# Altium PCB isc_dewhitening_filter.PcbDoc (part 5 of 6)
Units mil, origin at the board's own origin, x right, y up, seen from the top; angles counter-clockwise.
Board outline 8440 x 7000 mil, 6 copper layers (Top Layer, MidLayer1, InternalPlane1, Internal Plane 3, InternalPlane2, Bottom Layer); 550 components, 462 nets, 2189 pads, 795 vias.
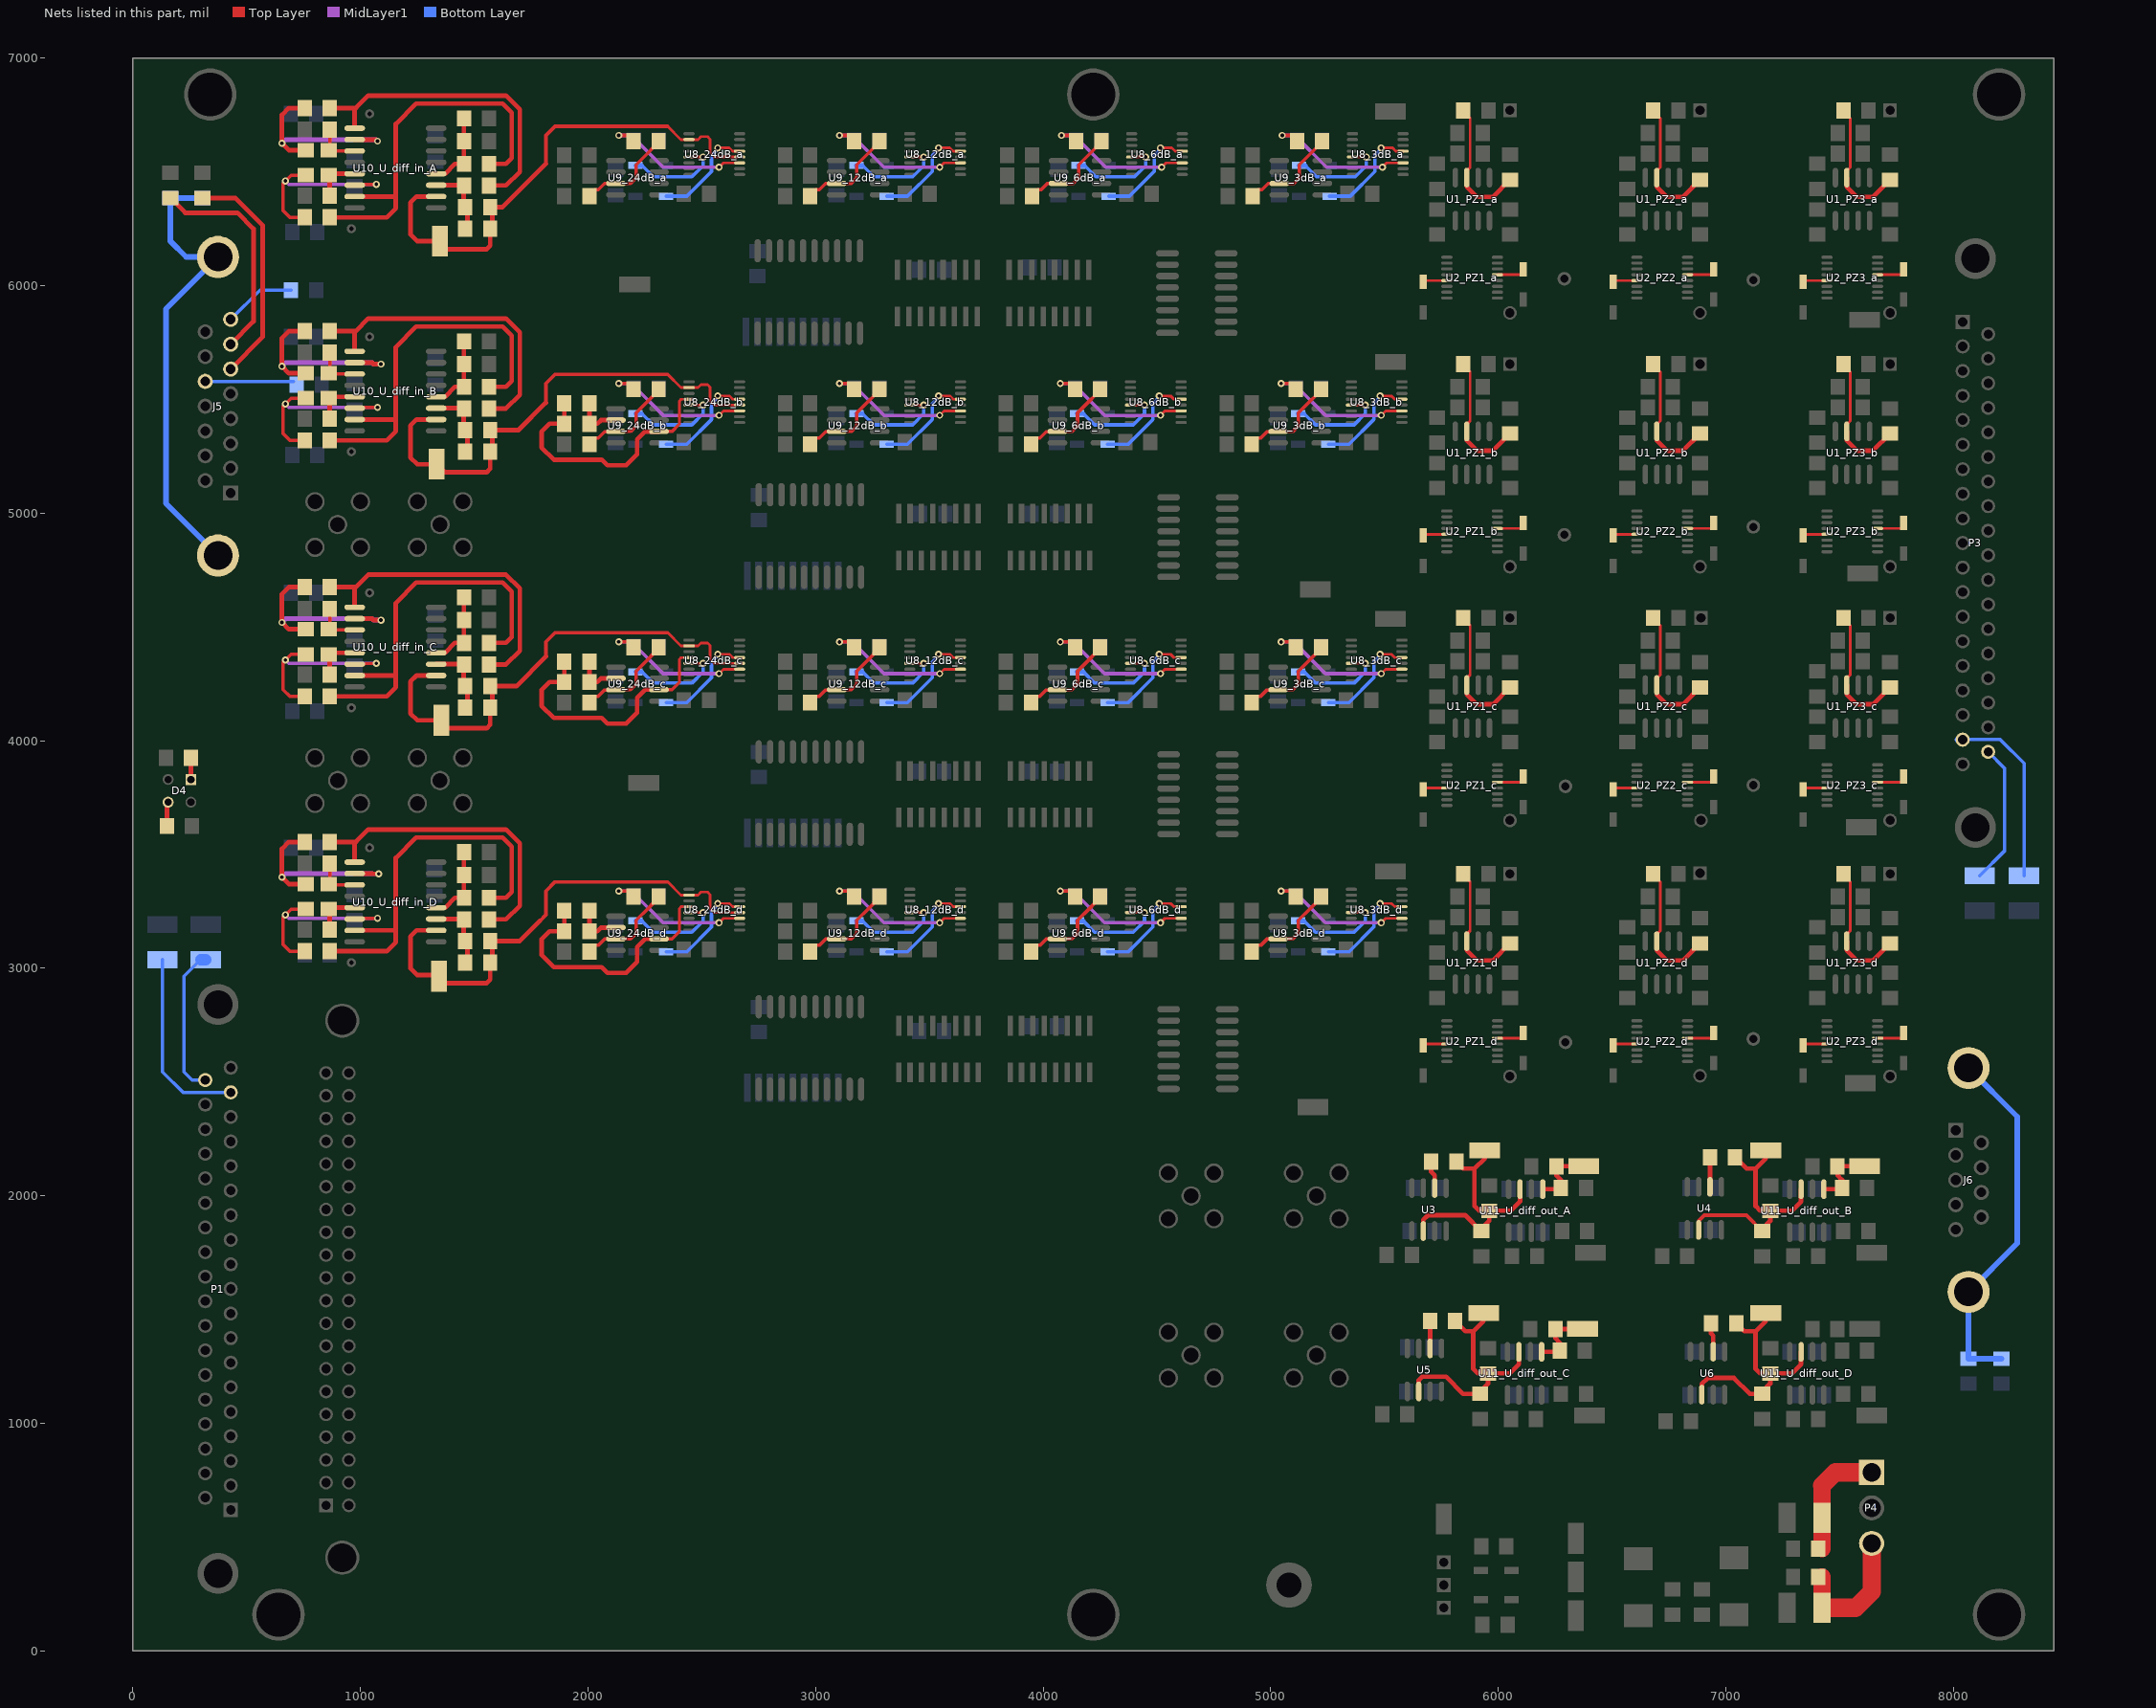
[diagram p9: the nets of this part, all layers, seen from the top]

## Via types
v1: diameter 31, hole 16, Top Layer to Bottom Layer, 794 vias
v2: diameter 45, hole 20, Top Layer to Bottom Layer, 1 vias

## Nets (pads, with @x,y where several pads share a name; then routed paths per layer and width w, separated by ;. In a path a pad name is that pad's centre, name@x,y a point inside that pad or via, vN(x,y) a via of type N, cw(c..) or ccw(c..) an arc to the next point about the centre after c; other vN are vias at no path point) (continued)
NetC27_24dB_b_1: C27_24dB_b.1 R13_24dB_b.2 U8_24dB_b.12 U9_24dB_b.6 | length 1154.7
  Top Layer w12: 2401,5391 2401,5492.5 2409.09,5500.59 U8_24dB_b.12@2426.67,5500.59
  Top Layer w15: U9_24dB_b.6@2311.49,5359 2369,5359 2401,5391
  Top Layer w20: C27_24dB_b.1@1895.88,5483 R13_24dB_b.2@1895.88,5393 1831,5393 1796,5358 1796,5289 1850,5235 2060,5235 2085,5210 2168,5210 2216,5258 2216,5323 2252,5359 U9_24dB_b.6@2311.49,5359
NetC27_24dB_b_2: C27_24dB_b.2 R13_24dB_b.1 U9_24dB_b.2 | length 213
  Top Layer w20: C27_24dB_b.2@2006.12,5483 R13_24dB_b.1@2006.12,5393 2041,5393 2057,5409 U9_24dB_b.2@2122.51,5409
NetC27_24dB_c_1: C27_24dB_c.1 R13_24dB_c.2 U8_24dB_c.12 U9_24dB_c.6 | length 1154.7
  Top Layer w12: 2401,4256 2401,4357.5 2409.09,4365.59 U8_24dB_c.12@2426.67,4365.59
  Top Layer w15: U9_24dB_c.6@2311.49,4224 2369,4224 2401,4256
  Top Layer w20: C27_24dB_c.1@1895.88,4348 R13_24dB_c.2@1895.88,4258 1831,4258 1796,4223 1796,4154 1850,4100 2060,4100 2085,4075 2168,4075 2216,4123 2216,4188 2252,4224 U9_24dB_c.6@2311.49,4224
NetC27_24dB_c_2: C27_24dB_c.2 R13_24dB_c.1 U9_24dB_c.2 | length 213
  Top Layer w20: C27_24dB_c.2@2006.12,4348 R13_24dB_c.1@2006.12,4258 2041,4258 2057,4274 U9_24dB_c.2@2122.51,4274
NetC27_24dB_d_1: C27_24dB_d.1 R13_24dB_d.2 U8_24dB_d.12 U9_24dB_d.6 | length 1154.7
  Top Layer w12: 2401,3161 2401,3262.5 2409.09,3270.59 U8_24dB_d.12@2426.67,3270.59
  Top Layer w15: U9_24dB_d.6@2311.49,3129 2369,3129 2401,3161
  Top Layer w20: C27_24dB_d.1@1895.88,3253 R13_24dB_d.2@1895.88,3163 1831,3163 1796,3128 1796,3059 1850,3005 2060,3005 2085,2980 2168,2980 2216,3028 2216,3093 2252,3129 U9_24dB_d.6@2311.49,3129
NetC27_24dB_d_2: C27_24dB_d.2 R13_24dB_d.1 U9_24dB_d.2 | length 213
  Top Layer w20: C27_24dB_d.2@2006.12,3253 R13_24dB_d.1@2006.12,3163 2041,3163 2057,3179 U9_24dB_d.2@2122.51,3179
NetC34_2: C34.2 J5.16 J5.17 R34.2 | length 2069.1
  Bottom Layer w25: R34.2@305,6384.88 C34.2@165,6384.88 165,6195 234.09,6125.91 J5.17@374.02,6125.91 145,5896.89 145,5043.11 J5.16@374.02,4814.09
NetC35_2: C35.2 J6.10 J6.11 R37.2 | length 1599.1
  Bottom Layer w25: C35.2@8065,1285.12 R37.2@8210,1285.12 ; C35.2@8065.98,1285.12 J6.11@8065.98,1578.07 8280,1792.09 8280,2347.91 J6.10@8065.98,2561.93
NetC37_U_diff_in_A_2: C37_U_diff_in_A.2 R15_U_diff_in_A.1 R16_U_diff_in_A.1 U10_U_diff_in_A.12 | length 340.1
  Top Layer w20: U10_U_diff_in_A.12@1332.8,6491.5 1371.5,6491.5 1415,6535 R15_U_diff_in_A.1@1454.88,6535 R16_U_diff_in_A.1@1454.88,6635 C37_U_diff_in_A.2@1454.88,6735
NetC37_U_diff_in_B_2: C37_U_diff_in_B.2 R15_U_diff_in_B.1 R16_U_diff_in_B.1 U10_U_diff_in_B.12 | length 340.1
  Top Layer w20: U10_U_diff_in_B.12@1332.8,5511.5 1371.5,5511.5 1415,5555 R15_U_diff_in_B.1@1454.88,5555 R16_U_diff_in_B.1@1454.88,5655 C37_U_diff_in_B.2@1454.88,5755
NetC37_U_diff_in_C_2: C37_U_diff_in_C.2 R15_U_diff_in_C.1 R16_U_diff_in_C.1 U10_U_diff_in_C.12 | length 340.1
  Top Layer w20: U10_U_diff_in_C.12@1332.8,4386.5 1371.5,4386.5 1415,4430 R15_U_diff_in_C.1@1454.88,4430 R16_U_diff_in_C.1@1454.88,4530 C37_U_diff_in_C.2@1454.88,4630
NetC37_U_diff_in_D_2: C37_U_diff_in_D.2 R15_U_diff_in_D.1 R16_U_diff_in_D.1 U10_U_diff_in_D.12 | length 340.1
  Top Layer w20: U10_U_diff_in_D.12@1332.8,3266.5 1371.5,3266.5 1415,3310 R15_U_diff_in_D.1@1454.88,3310 R16_U_diff_in_D.1@1454.88,3410 C37_U_diff_in_D.2@1454.88,3510
NetC38_U_diff_in_A_1: C38_U_diff_in_A.1 R33_U_diff_in_A.1 U10_U_diff_in_A.3 | length 195.7
  Top Layer w15: C38_U_diff_in_A.1@863.62,6591.5 U10_U_diff_in_A.3@974.53,6591.5 ; C38_U_diff_in_A.1@865.12,6600.24 R33_U_diff_in_A.1@865.12,6685
NetC38_U_diff_in_A_2: C38_U_diff_in_A.2 R32_U_diff_in_A.1 U10_U_diff_in_A.5 | length 192.7
  Top Layer w20: R32_U_diff_in_A.1@865.12,6395 C38_U_diff_in_A.2@865.12,6479.76 ; C38_U_diff_in_A.2@866.61,6491.5 U10_U_diff_in_A.5@974.53,6491.5
NetC38_U_diff_in_B_1: C38_U_diff_in_B.1 R33_U_diff_in_B.1 U10_U_diff_in_B.3 | length 195.7
  Top Layer w15: C38_U_diff_in_B.1@863.62,5611.5 U10_U_diff_in_B.3@974.53,5611.5 ; C38_U_diff_in_B.1@865.12,5620.24 R33_U_diff_in_B.1@865.12,5705
NetC38_U_diff_in_B_2: C38_U_diff_in_B.2 R32_U_diff_in_B.1 U10_U_diff_in_B.5 | length 192.7
  Top Layer w20: R32_U_diff_in_B.1@865.12,5415 C38_U_diff_in_B.2@865.12,5499.76 ; C38_U_diff_in_B.2@866.61,5511.5 U10_U_diff_in_B.5@974.53,5511.5
NetC38_U_diff_in_C_1: C38_U_diff_in_C.1 R33_U_diff_in_C.1 U10_U_diff_in_C.3 | length 195.7
  Top Layer w15: C38_U_diff_in_C.1@863.62,4486.5 U10_U_diff_in_C.3@974.53,4486.5 ; C38_U_diff_in_C.1@865.12,4495.24 R33_U_diff_in_C.1@865.12,4580
NetC38_U_diff_in_C_2: C38_U_diff_in_C.2 R32_U_diff_in_C.1 U10_U_diff_in_C.5 | length 192.7
  Top Layer w20: R32_U_diff_in_C.1@865.12,4290 C38_U_diff_in_C.2@865.12,4374.76 ; C38_U_diff_in_C.2@866.61,4386.5 U10_U_diff_in_C.5@974.53,4386.5
NetC38_U_diff_in_D_1: C38_U_diff_in_D.1 R33_U_diff_in_D.1 U10_U_diff_in_D.3 | length 195.7
  Top Layer w15: C38_U_diff_in_D.1@863.62,3366.5 U10_U_diff_in_D.3@974.53,3366.5 ; C38_U_diff_in_D.1@865.12,3375.24 R33_U_diff_in_D.1@865.12,3460
NetC38_U_diff_in_D_2: C38_U_diff_in_D.2 R32_U_diff_in_D.1 U10_U_diff_in_D.5 | length 192.7
  Top Layer w20: R32_U_diff_in_D.1@865.12,3170 C38_U_diff_in_D.2@865.12,3254.76 ; C38_U_diff_in_D.2@866.61,3266.5 U10_U_diff_in_D.5@974.53,3266.5
NetC39_U_diff_in_A_1: C39_U_diff_in_A.1 R20_U_diff_in_A.2 R21_U_diff_in_A.1 U10_U_diff_in_A.11 | length 321
  Top Layer w20: U10_U_diff_in_A.11@1332.8,6441.5 R21_U_diff_in_A.1@1453.39,6441.5 ; R21_U_diff_in_A.1@1454.88,6440 R21_U_diff_in_A.1@1453.39,6441.5 ; C39_U_diff_in_A.1@1469.88,6250 1469.88,6330 1453.39,6346.5 R21_U_diff_in_A.1@1453.39,6441.5
NetC39_U_diff_in_A_2: C39_U_diff_in_A.2 R20_U_diff_in_A.1 TP1.1 U8_24dB_a.4 U8_24dB_a.10 U10_U_diff_in_A.10 | length 2232.6
  Top Layer w12: 2350,6700 2408.23,6641.77 U8_24dB_a.10@2443.78,6641.77 2483.23,6641.77 2496.46,6655 2525,6655 2536.5,6643.5 2536.5,6583.5 2555,6565 U8_24dB_a.4@2666.22,6565
  Top Layer w15: 1815,6535 1815,6660 1855,6700 2350,6700
  Top Layer w20: U10_U_diff_in_A.10@1332.8,6391.5 1246.5,6391.5 1220,6365 1220,6225 1250,6195 1335,6195 1370,6160 1555,6160 1570.12,6175.12 C39_U_diff_in_A.2@1570.12,6250 ; C39_U_diff_in_A.2@1580,6249.88 1580.12,6250 1580.12,6340 1575.12,6345 1625,6345 1815,6535
NetC39_U_diff_in_B_1: C39_U_diff_in_B.1 R20_U_diff_in_B.2 R21_U_diff_in_B.1 U10_U_diff_in_B.11 | length 321
  Top Layer w20: U10_U_diff_in_B.11@1332.8,5461.5 R21_U_diff_in_B.1@1453.39,5461.5 ; R21_U_diff_in_B.1@1454.88,5460 R21_U_diff_in_B.1@1453.39,5461.5 ; C39_U_diff_in_B.1@1469.88,5270 1469.88,5350 1453.39,5366.5 R21_U_diff_in_B.1@1453.39,5461.5
NetC39_U_diff_in_B_2: C39_U_diff_in_B.2 R20_U_diff_in_B.1 TP14.1 U8_24dB_b.4 U8_24dB_b.10 U10_U_diff_in_B.10 | length 2163.6
  Top Layer w12: 2350,5610 2408.23,5551.77 U8_24dB_b.10@2443.78,5551.77 2483.23,5551.77 2496.46,5565 2525,5565 2536.5,5553.5 2536.5,5493.5 2555,5475 U8_24dB_b.4@2666.22,5475
  Top Layer w15: 1815,5485 1815,5570 1855,5610 2350,5610
  Top Layer w20: U10_U_diff_in_B.10@1332.8,5411.5 1246.5,5411.5 1220,5385 1220,5245 1250,5215 TP14.1@1335,5215 1370,5180 1555,5180 1570.12,5195.12 C39_U_diff_in_B.2@1570.12,5270 ; C39_U_diff_in_B.2@1580,5269.88 1580.12,5270 1580.12,5360 1575.12,5365 1695,5365 1815,5485
NetC39_U_diff_in_C_1: C39_U_diff_in_C.1 R20_U_diff_in_C.2 R21_U_diff_in_C.1 U10_U_diff_in_C.11 | length 321
  Top Layer w20: U10_U_diff_in_C.11@1332.8,4336.5 R21_U_diff_in_C.1@1453.39,4336.5 ; R21_U_diff_in_C.1@1454.88,4335 R21_U_diff_in_C.1@1453.39,4336.5 ; C39_U_diff_in_C.1@1469.88,4145 1469.88,4225 1453.39,4241.5 R21_U_diff_in_C.1@1453.39,4336.5
NetC39_U_diff_in_C_2: C39_U_diff_in_C.2 R20_U_diff_in_C.1 TP17.1 U8_24dB_c.4 U8_24dB_c.10 U10_U_diff_in_C.10 | length 2100
  Top Layer w12: 2350,4475 2408.23,4416.77 U8_24dB_c.10@2443.78,4416.77 2483.23,4416.77 2496.46,4430 2525,4430 2536.5,4418.5 2536.5,4358.5 2555,4340 U8_24dB_c.4@2666.22,4340
  Top Layer w15: 1815,4370 1815,4435 1855,4475 2350,4475
  Top Layer w20: U10_U_diff_in_C.10@1332.8,4286.5 1246.5,4286.5 1220,4260 1220,4120 1250,4090 TP17.1@1335,4090 ; TP17.1@1370,4055 1555,4055 1570.12,4070.12 C39_U_diff_in_C.2@1570.12,4145 ; C39_U_diff_in_C.2@1580,4144.88 1580.12,4145 1580.12,4235 1575.12,4240 1685,4240 1815,4370 1816.25,4371.25
NetC39_U_diff_in_D_1: C39_U_diff_in_D.1 R20_U_diff_in_D.2 R21_U_diff_in_D.1 U10_U_diff_in_D.11 | length 321
  Top Layer w20: U10_U_diff_in_D.11@1332.8,3216.5 R21_U_diff_in_D.1@1453.39,3216.5 ; R21_U_diff_in_D.1@1454.88,3215 R21_U_diff_in_D.1@1453.39,3216.5 ; C39_U_diff_in_D.1@1469.88,3025 1469.88,3105 1453.39,3121.5 R21_U_diff_in_D.1@1453.39,3216.5
NetC39_U_diff_in_D_2: C39_U_diff_in_D.2 R20_U_diff_in_D.1 TP20.1 U8_24dB_d.4 U8_24dB_d.10 U10_U_diff_in_D.10 | length 2132
  Top Layer w12: 2350,3380 2408.23,3321.77 U8_24dB_d.10@2443.78,3321.77 2483.23,3321.77 2496.46,3335 2525,3335 2536.5,3323.5 2536.5,3263.5 2555,3245 U8_24dB_d.4@2666.22,3245
  Top Layer w15: 1787.5,3207.5 1815,3235 1815,3340 1855,3380 2350,3380
  Top Layer w20: U10_U_diff_in_D.10@1332.8,3166.5 1246.5,3166.5 1220,3140 1220,3000 1250,2970 TP20.1@1335,2970 ; TP20.1@1370,2935 1555,2935 1570.12,2950.12 C39_U_diff_in_D.2@1570.12,3025 ; C39_U_diff_in_D.2@1580,3024.88 1580.12,3025 1580.12,3115 1575.12,3120 1700,3120 1787.5,3207.5
NetD1_PZ1_a_1: D1_PZ1_a.1 U2_PZ1_a.5 | length 109
  Top Layer w12: D1_PZ1_a.1@5672.8,6022.2 U2_PZ1_a.5@5773.78,6022.2 ; D1_PZ1_a.1@5676.93,6031.95 D1_PZ1_a.1@5676.93,6040
NetD1_PZ1_b_1: D1_PZ1_b.1 U2_PZ1_b.5 | length 109
  Top Layer w12: D1_PZ1_b.1@5672.8,4907.2 U2_PZ1_b.5@5773.78,4907.2 ; D1_PZ1_b.1@5676.93,4916.95 D1_PZ1_b.1@5676.93,4925
NetD1_PZ1_c_1: D1_PZ1_c.1 U2_PZ1_c.5 | length 109
  Top Layer w12: D1_PZ1_c.1@5672.8,3792.2 U2_PZ1_c.5@5773.78,3792.2 ; D1_PZ1_c.1@5676.93,3801.95 D1_PZ1_c.1@5676.93,3810
NetD1_PZ1_d_1: D1_PZ1_d.1 U2_PZ1_d.5 | length 109
  Top Layer w12: D1_PZ1_d.1@5672.8,2667.2 U2_PZ1_d.5@5773.78,2667.2 ; D1_PZ1_d.1@5676.93,2676.95 D1_PZ1_d.1@5676.93,2685
NetD1_PZ2_a_1: D1_PZ2_a.1 U2_PZ2_a.5 | length 109
  Top Layer w12: D1_PZ2_a.1@6507.8,6022.2 U2_PZ2_a.5@6608.78,6022.2 ; D1_PZ2_a.1@6511.93,6031.95 D1_PZ2_a.1@6511.93,6040
NetD1_PZ2_b_1: D1_PZ2_b.1 U2_PZ2_b.5 | length 109
  Top Layer w12: D1_PZ2_b.1@6507.8,4907.2 U2_PZ2_b.5@6608.78,4907.2 ; D1_PZ2_b.1@6511.93,4916.95 D1_PZ2_b.1@6511.93,4925
NetD1_PZ2_c_1: D1_PZ2_c.1 U2_PZ2_c.5 | length 109
  Top Layer w12: D1_PZ2_c.1@6507.8,3792.2 U2_PZ2_c.5@6608.78,3792.2 ; D1_PZ2_c.1@6511.93,3801.95 D1_PZ2_c.1@6511.93,3810
NetD1_PZ2_d_1: D1_PZ2_d.1 U2_PZ2_d.5 | length 109
  Top Layer w12: D1_PZ2_d.1@6507.8,2667.2 U2_PZ2_d.5@6608.78,2667.2 ; D1_PZ2_d.1@6511.93,2676.95 D1_PZ2_d.1@6511.93,2685
NetD1_PZ3_a_1: D1_PZ3_a.1 U2_PZ3_a.5 | length 109
  Top Layer w12: D1_PZ3_a.1@7342.8,6022.2 U2_PZ3_a.5@7443.78,6022.2 ; D1_PZ3_a.1@7346.93,6031.95 D1_PZ3_a.1@7346.93,6040
NetD1_PZ3_b_1: D1_PZ3_b.1 U2_PZ3_b.5 | length 109
  Top Layer w12: D1_PZ3_b.1@7342.8,4907.2 U2_PZ3_b.5@7443.78,4907.2 ; D1_PZ3_b.1@7346.93,4916.95 D1_PZ3_b.1@7346.93,4925
NetD1_PZ3_c_1: D1_PZ3_c.1 U2_PZ3_c.5 | length 109
  Top Layer w12: D1_PZ3_c.1@7342.8,3792.2 U2_PZ3_c.5@7443.78,3792.2 ; D1_PZ3_c.1@7346.93,3801.95 D1_PZ3_c.1@7346.93,3810
NetD1_PZ3_d_1: D1_PZ3_d.1 U2_PZ3_d.5 | length 109
  Top Layer w12: D1_PZ3_d.1@7342.8,2667.2 U2_PZ3_d.5@7443.78,2667.2 ; D1_PZ3_d.1@7346.93,2676.95 D1_PZ3_d.1@7346.93,2685
NetD2_PZ1_a_2: D2_PZ1_a.2 U2_PZ1_a.13 | length 132.2
  Top Layer w12: U2_PZ1_a.13@5996.22,6047.8 6100.25,6047.8 6110,6057.54 D2_PZ1_a.2@6110,6071.93
NetD2_PZ1_b_2: D2_PZ1_b.2 U2_PZ1_b.13 | length 132.2
  Top Layer w12: U2_PZ1_b.13@5996.22,4932.8 6100.25,4932.8 6110,4942.54 D2_PZ1_b.2@6110,4956.93
NetD2_PZ1_c_2: D2_PZ1_c.2 U2_PZ1_c.13 | length 132.2
  Top Layer w12: U2_PZ1_c.13@5996.22,3817.8 6100.25,3817.8 6110,3827.54 D2_PZ1_c.2@6110,3841.93
NetD2_PZ1_d_2: D2_PZ1_d.2 U2_PZ1_d.13 | length 132.2
  Top Layer w12: U2_PZ1_d.13@5996.22,2692.8 6100.25,2692.8 6110,2702.54 D2_PZ1_d.2@6110,2716.93
NetD2_PZ2_a_2: D2_PZ2_a.2 U2_PZ2_a.13 | length 132.2
  Top Layer w12: U2_PZ2_a.13@6831.22,6047.8 6935.25,6047.8 6945,6057.54 D2_PZ2_a.2@6945,6071.93
NetD2_PZ2_b_2: D2_PZ2_b.2 U2_PZ2_b.13 | length 132.2
  Top Layer w12: U2_PZ2_b.13@6831.22,4932.8 6935.25,4932.8 6945,4942.54 D2_PZ2_b.2@6945,4956.93
NetD2_PZ2_c_2: D2_PZ2_c.2 U2_PZ2_c.13 | length 132.2
  Top Layer w12: U2_PZ2_c.13@6831.22,3817.8 6935.25,3817.8 6945,3827.54 D2_PZ2_c.2@6945,3841.93
NetD2_PZ2_d_2: D2_PZ2_d.2 U2_PZ2_d.13 | length 132.2
  Top Layer w12: U2_PZ2_d.13@6831.22,2692.8 6935.25,2692.8 6945,2702.54 D2_PZ2_d.2@6945,2716.93
NetD2_PZ3_a_2: D2_PZ3_a.2 U2_PZ3_a.13 | length 132.2
  Top Layer w12: U2_PZ3_a.13@7666.22,6047.8 7770.25,6047.8 7780,6057.54 D2_PZ3_a.2@7780,6071.93
NetD2_PZ3_b_2: D2_PZ3_b.2 U2_PZ3_b.13 | length 132.2
  Top Layer w12: U2_PZ3_b.13@7666.22,4932.8 7770.25,4932.8 7780,4942.54 D2_PZ3_b.2@7780,4956.93
NetD2_PZ3_c_2: D2_PZ3_c.2 U2_PZ3_c.13 | length 132.2
  Top Layer w12: U2_PZ3_c.13@7666.22,3817.8 7770.25,3817.8 7780,3827.54 D2_PZ3_c.2@7780,3841.93
NetD2_PZ3_d_2: D2_PZ3_d.2 U2_PZ3_d.13 | length 132.2
  Top Layer w12: U2_PZ3_d.13@7666.22,2692.8 7770.25,2692.8 7780,2702.54 D2_PZ3_d.2@7780,2716.93
NetD4_1: D4.1 R10.1 | length 94.9
  Top Layer w20: D4.1@255,3830 R10.1@255,3924.88
NetD4_4: D4.4 R9.1 | length 107.1
  Top Layer w20: R9.1@149.88,3625 149.88,3724.88 D4.4@155,3730
NetD6_3dB_a_1: D6_3dB_a.1 U8_3dB_a.5 | length 461.6
  Top Layer w12: v1(5485,6605) 5535,6605 5549.41,6590.59 U8_3dB_a.5@5581.22,6590.59
  Bottom Layer w15: D6_3dB_a.1@5257.93,6393 5349,6393 5457.5,6501.5 5457.5,6571.5 5477,6591 5477,6592.67 5485,6600.67 v1(5485,6605)
NetD6_3dB_b_1: D6_3dB_b.1 U8_3dB_b.5 | length 461.6
  Top Layer w12: v1(5480,5515) 5530,5515 5544.41,5500.59 U8_3dB_b.5@5576.22,5500.59
  Bottom Layer w15: D6_3dB_b.1@5252.93,5303 5344,5303 5452.5,5411.5 5452.5,5481.5 5472,5501 5472,5502.67 5480,5510.67 v1(5480,5515)
NetD6_3dB_c_1: D6_3dB_c.1 U8_3dB_c.5 | length 461.6
  Top Layer w12: v1(5480,4380) 5530,4380 5544.41,4365.59 U8_3dB_c.5@5576.22,4365.59
  Bottom Layer w15: D6_3dB_c.1@5252.93,4168 5344,4168 5452.5,4276.5 5452.5,4346.5 5472,4366 5472,4367.67 5480,4375.67 v1(5480,4380)
NetD6_3dB_d_1: D6_3dB_d.1 U8_3dB_d.5 | length 461.6
  Top Layer w12: v1(5480,3285) 5530,3285 5544.41,3270.59 U8_3dB_d.5@5576.22,3270.59
  Bottom Layer w15: D6_3dB_d.1@5252.93,3073 5344,3073 5452.5,3181.5 5452.5,3251.5 5472,3271 5472,3272.67 5480,3280.67 v1(5480,3285)
NetD6_6dB_a_1: D6_6dB_a.1 U8_6dB_a.5 | length 461.6
  Top Layer w12: v1(4515,6605) 4565,6605 4579.41,6590.59 U8_6dB_a.5@4611.22,6590.59
  Bottom Layer w15: D6_6dB_a.1@4287.93,6393 4379,6393 4487.5,6501.5 4487.5,6571.5 4507,6591 4507,6592.67 4515,6600.67 v1(4515,6605)
NetD6_6dB_b_1: D6_6dB_b.1 U8_6dB_b.5 | length 461.6
  Top Layer w12: v1(4510,5515) 4560,5515 4574.41,5500.59 U8_6dB_b.5@4606.22,5500.59
  Bottom Layer w15: D6_6dB_b.1@4282.93,5303 4374,5303 4482.5,5411.5 4482.5,5481.5 4502,5501 4502,5502.67 4510,5510.67 v1(4510,5515)
NetD6_6dB_c_1: D6_6dB_c.1 U8_6dB_c.5 | length 461.6
  Top Layer w12: v1(4510,4380) 4560,4380 4574.41,4365.59 U8_6dB_c.5@4606.22,4365.59
  Bottom Layer w15: D6_6dB_c.1@4282.93,4168 4374,4168 4482.5,4276.5 4482.5,4346.5 4502,4366 4502,4367.67 4510,4375.67 v1(4510,4380)
NetD6_6dB_d_1: D6_6dB_d.1 U8_6dB_d.5 | length 461.6
  Top Layer w12: v1(4510,3285) 4560,3285 4574.41,3270.59 U8_6dB_d.5@4606.22,3270.59
  Bottom Layer w15: D6_6dB_d.1@4282.93,3073 4374,3073 4482.5,3181.5 4482.5,3251.5 4502,3271 4502,3272.67 4510,3280.67 v1(4510,3285)
NetD6_12dB_a_1: D6_12dB_a.1 U8_12dB_a.5 | length 461.6
  Top Layer w12: v1(3540,6605) 3590,6605 3604.41,6590.59 U8_12dB_a.5@3636.22,6590.59
  Bottom Layer w15: D6_12dB_a.1@3312.93,6393 3404,6393 3512.5,6501.5 3512.5,6571.5 3532,6591 3532,6592.67 3540,6600.67 v1(3540,6605)
NetD6_12dB_b_1: D6_12dB_b.1 U8_12dB_b.5 | length 461.6
  Top Layer w12: v1(3540,5515) 3590,5515 3604.41,5500.59 U8_12dB_b.5@3636.22,5500.59
  Bottom Layer w15: D6_12dB_b.1@3312.93,5303 3404,5303 3512.5,5411.5 3512.5,5481.5 3532,5501 3532,5502.67 3540,5510.67 v1(3540,5515)
NetD6_12dB_c_1: D6_12dB_c.1 U8_12dB_c.5 | length 461.6
  Top Layer w12: v1(3540,4380) 3590,4380 3604.41,4365.59 U8_12dB_c.5@3636.22,4365.59
  Bottom Layer w15: D6_12dB_c.1@3312.93,4168 3404,4168 3512.5,4276.5 3512.5,4346.5 3532,4366 3532,4367.67 3540,4375.67 v1(3540,4380)
NetD6_12dB_d_1: D6_12dB_d.1 U8_12dB_d.5 | length 461.6
  Top Layer w12: v1(3540,3285) 3590,3285 3604.41,3270.59 U8_12dB_d.5@3636.22,3270.59
  Bottom Layer w15: D6_12dB_d.1@3312.93,3073 3404,3073 3512.5,3181.5 3512.5,3251.5 3532,3271 3532,3272.67 3540,3280.67 v1(3540,3285)
NetD6_24dB_a_1: D6_24dB_a.1 U8_24dB_a.5 | length 461.6
  Top Layer w12: v1(2570,6605) 2620,6605 2634.41,6590.59 U8_24dB_a.5@2666.22,6590.59
  Bottom Layer w15: D6_24dB_a.1@2342.93,6393 2434,6393 2542.5,6501.5 2542.5,6571.5 2562,6591 2562,6592.67 2570,6600.67 v1(2570,6605)
NetD6_24dB_b_1: D6_24dB_b.1 U8_24dB_b.5 | length 461.6
  Top Layer w12: v1(2570,5515) 2620,5515 2634.41,5500.59 U8_24dB_b.5@2666.22,5500.59
  Bottom Layer w15: D6_24dB_b.1@2342.93,5303 2434,5303 2542.5,5411.5 2542.5,5481.5 2562,5501 2562,5502.67 2570,5510.67 v1(2570,5515)
NetD6_24dB_c_1: D6_24dB_c.1 U8_24dB_c.5 | length 461.6
  Top Layer w12: v1(2570,4380) 2620,4380 2634.41,4365.59 U8_24dB_c.5@2666.22,4365.59
  Bottom Layer w15: D6_24dB_c.1@2342.93,4168 2434,4168 2542.5,4276.5 2542.5,4346.5 2562,4366 2562,4367.67 2570,4375.67 v1(2570,4380)
NetD6_24dB_d_1: D6_24dB_d.1 U8_24dB_d.5 | length 461.6
  Top Layer w12: v1(2570,3285) 2620,3285 2634.41,3270.59 U8_24dB_d.5@2666.22,3270.59
  Bottom Layer w15: D6_24dB_d.1@2342.93,3073 2434,3073 2542.5,3181.5 2542.5,3251.5 2562,3271 2562,3272.67 2570,3280.67 v1(2570,3285)
NetD7_3dB_a_2: D7_3dB_a.2 U8_3dB_a.13 | length 436.2
  Top Layer w12: U8_3dB_a.13@5358.78,6565 v1(5420,6565)
  Bottom Layer w15: D7_3dB_a.2@5151,6528 5201,6478 5371,6478 5420,6527 v1(5420,6565)
  Bottom Layer w20: D7_3dB_a.2@5124.07,6528 D7_3dB_a.2@5151,6528
NetD7_3dB_b_2: D7_3dB_b.2 U8_3dB_b.13 | length 436.2
  Top Layer w12: U8_3dB_b.13@5353.78,5475 v1(5415,5475)
  Bottom Layer w15: D7_3dB_b.2@5146,5438 5196,5388 5366,5388 5415,5437 v1(5415,5475)
  Bottom Layer w20: D7_3dB_b.2@5119.07,5438 D7_3dB_b.2@5146,5438
NetD7_3dB_c_2: D7_3dB_c.2 U8_3dB_c.13 | length 436.2
  Top Layer w12: U8_3dB_c.13@5353.78,4340 v1(5415,4340)
  Bottom Layer w15: D7_3dB_c.2@5146,4303 5196,4253 5366,4253 5415,4302 v1(5415,4340)
  Bottom Layer w20: D7_3dB_c.2@5119.07,4303 D7_3dB_c.2@5146,4303
NetD7_3dB_d_2: D7_3dB_d.2 U8_3dB_d.13 | length 436.2
  Top Layer w12: U8_3dB_d.13@5353.78,3245 v1(5415,3245)
  Bottom Layer w15: D7_3dB_d.2@5146,3208 5196,3158 5366,3158 5415,3207 v1(5415,3245)
  Bottom Layer w20: D7_3dB_d.2@5119.07,3208 D7_3dB_d.2@5146,3208
NetD7_6dB_a_2: D7_6dB_a.2 U8_6dB_a.13 | length 436.2
  Top Layer w12: U8_6dB_a.13@4388.78,6565 v1(4450,6565)
  Bottom Layer w15: D7_6dB_a.2@4181,6528 4231,6478 4401,6478 4450,6527 v1(4450,6565)
  Bottom Layer w20: D7_6dB_a.2@4154.07,6528 D7_6dB_a.2@4181,6528
NetD7_6dB_b_2: D7_6dB_b.2 U8_6dB_b.13 | length 436.2
  Top Layer w12: U8_6dB_b.13@4383.78,5475 v1(4445,5475)
  Bottom Layer w15: D7_6dB_b.2@4176,5438 4226,5388 4396,5388 4445,5437 v1(4445,5475)
  Bottom Layer w20: D7_6dB_b.2@4149.07,5438 D7_6dB_b.2@4176,5438
NetD7_6dB_c_2: D7_6dB_c.2 U8_6dB_c.13 | length 436.2
  Top Layer w12: U8_6dB_c.13@4383.78,4340 v1(4445,4340)
  Bottom Layer w15: D7_6dB_c.2@4176,4303 4226,4253 4396,4253 4445,4302 v1(4445,4340)
  Bottom Layer w20: D7_6dB_c.2@4149.07,4303 D7_6dB_c.2@4176,4303
NetD7_6dB_d_2: D7_6dB_d.2 U8_6dB_d.13 | length 436.2
  Top Layer w12: U8_6dB_d.13@4383.78,3245 v1(4445,3245)
  Bottom Layer w15: D7_6dB_d.2@4176,3208 4226,3158 4396,3158 4445,3207 v1(4445,3245)
  Bottom Layer w20: D7_6dB_d.2@4149.07,3208 D7_6dB_d.2@4176,3208
NetD7_12dB_a_2: D7_12dB_a.2 U8_12dB_a.13 | length 436.2
  Top Layer w12: U8_12dB_a.13@3413.78,6565 v1(3475,6565)
  Bottom Layer w15: D7_12dB_a.2@3206,6528 3256,6478 3426,6478 3475,6527 v1(3475,6565)
  Bottom Layer w20: D7_12dB_a.2@3179.07,6528 D7_12dB_a.2@3206,6528
NetD7_12dB_b_2: D7_12dB_b.2 U8_12dB_b.13 | length 436.2
  Top Layer w12: U8_12dB_b.13@3413.78,5475 v1(3475,5475)
  Bottom Layer w15: D7_12dB_b.2@3206,5438 3256,5388 3426,5388 3475,5437 v1(3475,5475)
  Bottom Layer w20: D7_12dB_b.2@3179.07,5438 D7_12dB_b.2@3206,5438
NetD7_12dB_c_2: D7_12dB_c.2 U8_12dB_c.13 | length 436.2
  Top Layer w12: U8_12dB_c.13@3413.78,4340 v1(3475,4340)
  Bottom Layer w15: D7_12dB_c.2@3206,4303 3256,4253 3426,4253 3475,4302 v1(3475,4340)
  Bottom Layer w20: D7_12dB_c.2@3179.07,4303 D7_12dB_c.2@3206,4303
NetD7_12dB_d_2: D7_12dB_d.2 U8_12dB_d.13 | length 436.2
  Top Layer w12: U8_12dB_d.13@3413.78,3245 v1(3475,3245)
  Bottom Layer w15: D7_12dB_d.2@3206,3208 3256,3158 3426,3158 3475,3207 v1(3475,3245)
  Bottom Layer w20: D7_12dB_d.2@3179.07,3208 D7_12dB_d.2@3206,3208
NetD7_24dB_a_2: D7_24dB_a.2 U8_24dB_a.13 | length 436.2
  Top Layer w12: U8_24dB_a.13@2443.78,6565 v1(2505,6565)
  Bottom Layer w15: D7_24dB_a.2@2236,6528 2286,6478 2456,6478 2505,6527 v1(2505,6565)
  Bottom Layer w20: D7_24dB_a.2@2209.07,6528 D7_24dB_a.2@2236,6528
NetD7_24dB_b_2: D7_24dB_b.2 U8_24dB_b.13 | length 436.2
  Top Layer w12: U8_24dB_b.13@2443.78,5475 v1(2505,5475)
  Bottom Layer w15: D7_24dB_b.2@2236,5438 2286,5388 2456,5388 2505,5437 v1(2505,5475)
  Bottom Layer w20: D7_24dB_b.2@2209.07,5438 D7_24dB_b.2@2236,5438
NetD7_24dB_c_2: D7_24dB_c.2 U8_24dB_c.13 | length 436.2
  Top Layer w12: U8_24dB_c.13@2443.78,4340 v1(2505,4340)
  Bottom Layer w15: D7_24dB_c.2@2236,4303 2286,4253 2456,4253 2505,4302 v1(2505,4340)
  Bottom Layer w20: D7_24dB_c.2@2209.07,4303 D7_24dB_c.2@2236,4303
NetD7_24dB_d_2: D7_24dB_d.2 U8_24dB_d.13 | length 436.2
  Top Layer w12: U8_24dB_d.13@2443.78,3245 v1(2505,3245)
  Bottom Layer w15: D7_24dB_d.2@2236,3208 2286,3158 2456,3158 2505,3207 v1(2505,3245)
  Bottom Layer w20: D7_24dB_d.2@2209.07,3208 D7_24dB_d.2@2236,3208
NetJ5_6: J5.6 R7.1 | length 1004.1
  Top Layer w20: R7.1@305,6384.88 450.12,6384.88 570,6265 570,5773.66 J5.6@429.92,5633.58
NetJ5_7: J5.7 R8.1 | length 969.7
  Top Layer w20: R8.1@165,6384.88 229.88,6320 460,6320 530,6250 530,5842.72 J5.7@429.92,5742.64
NetJ5_8: J5.8 R36.2 | length 318.1
  Bottom Layer w15: J5.8@429.92,5851.69 558.23,5980 R36.2@694.88,5980
NetJ5_13: J5.13 R35.1 | length 387.7
  Bottom Layer w15: J5.13@318.11,5579.06 R35.1@705.83,5579.06
NetL1_1: L1.1 P4.1 R38.1 | length 519.1
  Top Layer w75: R38.1@7421.77,450 L1.1@7421.77,585 7421.77,726.77
  Top Layer w80: 7421.77,726.77 7480,785 P4.1@7640,785
NetL2_1: L2.1 P4.3 R39.1 | length 590.2
  Top Layer w75: L2.1@7421.77,190 R39.1@7421.77,325
  Top Layer w80: L2.1@7426.77,190 7570,190 7640,260 P4.3@7640,473
NetL5_1: L5.1 P1.18 | length 830.5
  Bottom Layer w15: L5.1@130,3038.23 130,2545 220,2455 P1.18@430,2455
NetL6_1: L6.1 P1.37 | length 653.2
  Bottom Layer w15: L6.1@298.23,3038.23 225,2965 225,2545 261,2509 P1.37@318,2509
  Bottom Layer w50: L6.1@298.23,3038.23 L6.1@320,3038.23
NetL7_1: L7.1 P3.18 | length 826.7
  Bottom Layer w15: P3.18@8040,4005 8205,4005 8310,3900 L7.1@8310,3406.77
  Bottom Layer w30: P3.18@8020,4005 P3.18@8040,4005
NetL8_1: L8.1 P3.37 | length 620
  Bottom Layer w15: L8.1@8115,3406.77 8225,3516.77 8225,3878 P3.37@8152,3951
NetR2_PZ1_a_2: R2_PZ1_a.2 R30_PZ1_a.1 U1_PZ1_a.3 | length 593.9
  Top Layer w12: R2_PZ1_a.2@5845.88,6770 5845.88,6766.06 5876,6735.94 5876,6519.82 5861,6504.82 U1_PZ1_a.3@5861,6474.49
  Top Layer w20: U1_PZ1_a.3@5861,6474.49 5861,6434 5905,6390 5976.12,6390 R30_PZ1_a.1@6051,6464.88
NetR2_PZ1_b_2: R2_PZ1_b.2 R30_PZ1_b.1 U1_PZ1_b.3 | length 593.9
  Top Layer w12: R2_PZ1_b.2@5845.88,5655 5845.88,5651.06 5876,5620.94 5876,5404.82 5861,5389.82 U1_PZ1_b.3@5861,5359.49
  Top Layer w20: U1_PZ1_b.3@5861,5359.49 5861,5319 5905,5275 5976.12,5275 R30_PZ1_b.1@6051,5349.88
NetR2_PZ1_c_2: R2_PZ1_c.2 R30_PZ1_c.1 U1_PZ1_c.3 | length 593.9
  Top Layer w12: R2_PZ1_c.2@5845.88,4540 5845.88,4536.06 5876,4505.94 5876,4289.82 5861,4274.82 U1_PZ1_c.3@5861,4244.49
  Top Layer w20: U1_PZ1_c.3@5861,4244.49 5861,4204 5905,4160 5976.12,4160 R30_PZ1_c.1@6051,4234.88
NetR2_PZ1_d_2: R2_PZ1_d.2 R30_PZ1_d.1 U1_PZ1_d.3 | length 593.9
  Top Layer w12: R2_PZ1_d.2@5845.88,3415 5845.88,3411.06 5876,3380.94 5876,3164.82 5861,3149.82 U1_PZ1_d.3@5861,3119.49
  Top Layer w20: U1_PZ1_d.3@5861,3119.49 5861,3079 5905,3035 5976.12,3035 R30_PZ1_d.1@6051,3109.88
NetR2_PZ2_a_2: R2_PZ2_a.2 R30_PZ2_a.1 U1_PZ2_a.3 | length 593.9
  Top Layer w12: R2_PZ2_a.2@6680.88,6770 6680.88,6766.06 6711,6735.94 6711,6519.82 6696,6504.82 U1_PZ2_a.3@6696,6474.49
  Top Layer w20: U1_PZ2_a.3@6696,6474.49 6696,6434 6740,6390 6811.12,6390 R30_PZ2_a.1@6886,6464.88
NetR2_PZ2_b_2: R2_PZ2_b.2 R30_PZ2_b.1 U1_PZ2_b.3 | length 593.9
  Top Layer w12: R2_PZ2_b.2@6680.88,5655 6680.88,5651.06 6711,5620.94 6711,5404.82 6696,5389.82 U1_PZ2_b.3@6696,5359.49
  Top Layer w20: U1_PZ2_b.3@6696,5359.49 6696,5319 6740,5275 6811.12,5275 R30_PZ2_b.1@6886,5349.88
NetR2_PZ2_c_2: R2_PZ2_c.2 R30_PZ2_c.1 U1_PZ2_c.3 | length 593.9
  Top Layer w12: R2_PZ2_c.2@6680.88,4540 6680.88,4536.06 6711,4505.94 6711,4289.82 6696,4274.82 U1_PZ2_c.3@6696,4244.49
  Top Layer w20: U1_PZ2_c.3@6696,4244.49 6696,4204 6740,4160 6811.12,4160 R30_PZ2_c.1@6886,4234.88
NetR2_PZ2_d_2: R2_PZ2_d.2 R30_PZ2_d.1 U1_PZ2_d.3 | length 593.9
  Top Layer w12: R2_PZ2_d.2@6680.88,3415 6680.88,3411.06 6711,3380.94 6711,3164.82 6696,3149.82 U1_PZ2_d.3@6696,3119.49
  Top Layer w20: U1_PZ2_d.3@6696,3119.49 6696,3079 6740,3035 6811.12,3035 R30_PZ2_d.1@6886,3109.88
NetR2_PZ3_a_2: R2_PZ3_a.2 R30_PZ3_a.1 U1_PZ3_a.3 | length 593.9
  Top Layer w12: R2_PZ3_a.2@7515.88,6770 7515.88,6766.06 7546,6735.94 7546,6519.82 7531,6504.82 U1_PZ3_a.3@7531,6474.49
  Top Layer w20: U1_PZ3_a.3@7531,6474.49 7531,6434 7575,6390 7646.12,6390 R30_PZ3_a.1@7721,6464.88
NetR2_PZ3_b_2: R2_PZ3_b.2 R30_PZ3_b.1 U1_PZ3_b.3 | length 593.9
  Top Layer w12: R2_PZ3_b.2@7515.88,5655 7515.88,5651.06 7546,5620.94 7546,5404.82 7531,5389.82 U1_PZ3_b.3@7531,5359.49
  Top Layer w20: U1_PZ3_b.3@7531,5359.49 7531,5319 7575,5275 7646.12,5275 R30_PZ3_b.1@7721,5349.88
NetR2_PZ3_c_2: R2_PZ3_c.2 R30_PZ3_c.1 U1_PZ3_c.3 | length 593.9
  Top Layer w12: R2_PZ3_c.2@7515.88,4540 7515.88,4536.06 7546,4505.94 7546,4289.82 7531,4274.82 U1_PZ3_c.3@7531,4244.49
  Top Layer w20: U1_PZ3_c.3@7531,4244.49 7531,4204 7575,4160 7646.12,4160 R30_PZ3_c.1@7721,4234.88
NetR2_PZ3_d_2: R2_PZ3_d.2 R30_PZ3_d.1 U1_PZ3_d.3 | length 593.9
  Top Layer w12: R2_PZ3_d.2@7515.88,3415 7515.88,3411.06 7546,3380.94 7546,3164.82 7531,3149.82 U1_PZ3_d.3@7531,3119.49
  Top Layer w20: U1_PZ3_d.3@7531,3119.49 7531,3079 7575,3035 7646.12,3035 R30_PZ3_d.1@7721,3109.88
NetR3_1: R3.1 U3.2 | length 121.8
  Top Layer w20: R3.1@5704.88,2150 5704.88,2105.12 5720,2090 U3.2@5720,2034.49
NetR3_2: R3.2 R24_U_diff_out_A.1 R27_U_diff_out_A.1 TP8_U_diff_out_A.1 U3.6 U11_U_diff_out_A.3 | length 1081.4
  Top Layer w20: U3.6@5670,1845.51 5670,1895 5690,1915 5855.12,1915 R27_U_diff_out_A.1@5925,1845.12 5925,1855 5960,1890 R24_U_diff_out_A.1@5960,1934.88 ; R3.2@5815.12,2150 5845.12,2120 5895,2120 ; TP8_U_diff_out_A.1@5940,2200 5940,2165 5895,2120 ; U11_U_diff_out_A.3@6095,2029.49 6095,1975 6054.88,1934.88 R24_U_diff_out_A.1@5960,1934.88 ; 5895,2120 5895,1955 5915.12,1934.88 R24_U_diff_out_A.1@5960,1934.88
NetR4_1: R4.1 U4.2 | length 130.6
  Top Layer w20: R4.1@6929.88,2170 6930,2169.88 U4.2@6930,2039.49
NetR4_2: R4.2 R24_U_diff_out_B.1 R27_U_diff_out_B.1 TP8_U_diff_out_B.1 U4.6 U11_U_diff_out_B.3 | length 1116.7
  Top Layer w15: U4.6@6880,1850.51 6880,1890 6905,1915 7090.12,1915 R27_U_diff_out_B.1@7160,1845.12
  Top Layer w20: R4.2@7040.12,2170 7090.12,2120 7130,2120 ; R27_U_diff_out_B.1@7160,1845.12 7160,1855 7195,1890 R24_U_diff_out_B.1@7195,1934.88 ; TP8_U_diff_out_B.1@7175,2200 7175,2165 7130,2120 ; U11_U_diff_out_B.3@7330,2029.49 7330,1975 7289.88,1934.88 R24_U_diff_out_B.1@7195,1934.88 ; 7130,2120 7130,1955 7150.12,1934.88 R24_U_diff_out_B.1@7195,1934.88
NetR5_1: R5.1 U5.2 | length 105.6
  Top Layer w20: R5.1@5699.88,1435 5700,1434.88 U5.2@5700,1329.49
NetR5_2: R5.2 R24_U_diff_out_C.1 R27_U_diff_out_C.1 TP8_U_diff_out_C.1 U5.6 U11_U_diff_out_C.3 | length 1102.6
  Top Layer w20: U5.6@5650,1140.51 5650,1190 5665,1205 5770,1205 5844.88,1130.12 R27_U_diff_out_C.1@5920,1130.12 5920,1140 5955,1175 R24_U_diff_out_C.1@5955,1219.88 ; R5.2@5810.12,1450 5855.12,1405 5890,1405 ; TP8_U_diff_out_C.1@5935,1485 5935,1450 5890,1405 ; U11_U_diff_out_C.3@6090,1314.49 6090,1260 6049.88,1219.88 R24_U_diff_out_C.1@5955,1219.88 ; 5890,1405 5890,1240 5910.12,1219.88 R24_U_diff_out_C.1@5955,1219.88
NetR6_1: R6.1 U6.2 | length 128.3
  Top Layer w20: R6.1@6934.88,1440 6934.88,1395.12 6944,1386 U6.2@6944,1315.49
NetR6_2: R6.2 R24_U_diff_out_D.1 R27_U_diff_out_D.1 TP8_U_diff_out_D.1 U6.6 U11_U_diff_out_D.3 | length 1099.9
  Top Layer w20: U6.6@6894,1126.51 6894,1174 6920,1200 7035,1200 7104.88,1130.12 R27_U_diff_out_D.1@7160,1130.12 7160,1140 7195,1175 R24_U_diff_out_D.1@7195,1219.88 ; R6.2@7045.12,1440 7080.12,1405 7130,1405 ; TP8_U_diff_out_D.1@7175,1485 7175,1450 7130,1405 ; U11_U_diff_out_D.3@7330,1314.49 7330,1260 7289.88,1219.88 R24_U_diff_out_D.1@7195,1219.88 ; 7130,1405 7130,1240 7150.12,1219.88 R24_U_diff_out_D.1@7195,1219.88
NetR11_3dB_a_1: R11_3dB_a.1 R12_3dB_a.2 U9_3dB_a.3 | length 439.4
  Top Layer w15: R12_3dB_a.2@4921.12,6396.94 4945.11,6420.93 4960.93,6420.93 4988.25,6448.25 5036.76,6448.25 U9_3dB_a.3@5037.51,6449 5102,6449 5125.88,6472.88 5125.88,6530.54 5178.31,6582.97 5201.12,6605.78 5201.12,6611 R11_3dB_a.1@5225.12,6635
NetR11_3dB_a_2: R11_3dB_a.2 U8_3dB_a.3 | length 672.4
  Top Layer w12: v1(5490.5,6520) 5490.5,6520.5 5509.41,6539.41 U8_3dB_a.3@5581.22,6539.41
  Top Layer w15: v1(5050,6660) 5090.89,6660 R11_3dB_a.2@5114.88,6636
  MidLayer1 w15: v1(5050,6660) 5105,6660 5245,6520 v1(5490.5,6520)
NetR11_3dB_b_1: R11_3dB_b.1 R12_3dB_b.2 U9_3dB_b.3 | length 439.4
  Top Layer w15: R12_3dB_b.2@4916.12,5306.94 4940.11,5330.93 4955.93,5330.93 4983.25,5358.25 5031.76,5358.25 U9_3dB_b.3@5032.51,5359 5097,5359 5120.88,5382.88 5120.88,5440.54 5173.31,5492.97 5196.12,5515.78 5196.12,5521 R11_3dB_b.1@5220.12,5545
NetR11_3dB_b_2: R11_3dB_b.2 U8_3dB_b.3 | length 672.4
  Top Layer w12: v1(5485.5,5430) 5485.5,5430.5 5504.41,5449.41 U8_3dB_b.3@5576.22,5449.41
  Top Layer w15: v1(5045,5570) 5085.89,5570 R11_3dB_b.2@5109.88,5546
  MidLayer1 w15: v1(5045,5570) 5100,5570 5240,5430 v1(5485.5,5430)
NetR11_3dB_c_1: R11_3dB_c.1 R12_3dB_c.2 U9_3dB_c.3 | length 438.4
  Top Layer w15: R12_3dB_c.2@4916.12,4171.94 4940.11,4195.93 4955.93,4195.93 4983.25,4223.25 U9_3dB_c.3@5031.76,4223.25 ; U9_3dB_c.3@5032.51,4224 5097,4224 5120.88,4247.88 5120.88,4305.54 5173.31,4357.97 5196.12,4380.78 5196.12,4386 R11_3dB_c.1@5220.12,4410
NetR11_3dB_c_2: R11_3dB_c.2 U8_3dB_c.3 | length 671.9
  Top Layer w12: v1(5485.5,4295) 5485.5,4295.5 5504.41,4314.41 U8_3dB_c.3@5576.22,4314.41
  Top Layer w15: v1(5045,4434) 5085.89,4434 R11_3dB_c.2@5109.88,4410
  MidLayer1 w15: v1(5045,4434) 5101,4434 5240,4295 v1(5485.5,4295)
NetR11_3dB_d_1: R11_3dB_d.1 R12_3dB_d.2 U9_3dB_d.3 | length 438.4
  Top Layer w15: R12_3dB_d.2@4916.12,3076.94 4940.11,3100.93 4955.93,3100.93 4983.25,3128.25 U9_3dB_d.3@5031.76,3128.25 ; U9_3dB_d.3@5032.51,3129 5097,3129 5120.88,3152.88 5120.88,3210.54 5173.31,3262.97 5196.12,3285.78 5196.12,3291 R11_3dB_d.1@5220.12,3315
NetR11_3dB_d_2: R11_3dB_d.2 U8_3dB_d.3 | length 671.9
  Top Layer w12: v1(5485.5,3200) 5485.5,3200.5 5504.41,3219.41 U8_3dB_d.3@5576.22,3219.41
  Top Layer w15: v1(5045,3339) 5085.89,3339 R11_3dB_d.2@5109.88,3315
  MidLayer1 w15: v1(5045,3339) 5101,3339 5240,3200 v1(5485.5,3200)
NetR11_6dB_a_1: R11_6dB_a.1 R12_6dB_a.2 U9_6dB_a.3 | length 439.4
  Top Layer w15: R12_6dB_a.2@3951.12,6396.94 3975.11,6420.93 3990.93,6420.93 4018.25,6448.25 4066.76,6448.25 U9_6dB_a.3@4067.51,6449 4132,6449 4155.88,6472.88 4155.88,6530.54 4208.31,6582.97 4231.12,6605.78 4231.12,6611 R11_6dB_a.1@4255.12,6635
NetR11_6dB_a_2: R11_6dB_a.2 U8_6dB_a.3 | length 672.4
  Top Layer w12: v1(4520.5,6520) 4520.5,6520.5 4539.41,6539.41 U8_6dB_a.3@4611.22,6539.41
  Top Layer w15: v1(4080,6660) 4120.89,6660 R11_6dB_a.2@4144.88,6636
  MidLayer1 w15: v1(4080,6660) 4135,6660 4275,6520 v1(4520.5,6520)
NetR11_6dB_b_1: R11_6dB_b.1 R12_6dB_b.2 U9_6dB_b.3 | length 439.4
  Top Layer w15: R12_6dB_b.2@3946.12,5306.94 3970.11,5330.93 3985.93,5330.93 4013.25,5358.25 4061.76,5358.25 U9_6dB_b.3@4062.51,5359 4127,5359 4150.88,5382.88 4150.88,5440.54 4203.31,5492.97 4226.12,5515.78 4226.12,5521 R11_6dB_b.1@4250.12,5545
NetR11_6dB_b_2: R11_6dB_b.2 U8_6dB_b.3 | length 672.4
  Top Layer w12: v1(4515.5,5430) 4515.5,5430.5 4534.41,5449.41 U8_6dB_b.3@4606.22,5449.41
  Top Layer w15: v1(4075,5570) 4115.89,5570 R11_6dB_b.2@4139.88,5546
  MidLayer1 w15: v1(4075,5570) 4130,5570 4270,5430 v1(4515.5,5430)
NetR11_6dB_c_1: R11_6dB_c.1 R12_6dB_c.2 U9_6dB_c.3 | length 438.4
  Top Layer w15: R12_6dB_c.2@3946.12,4171.94 3970.11,4195.93 3985.93,4195.93 4013.25,4223.25 U9_6dB_c.3@4061.76,4223.25 ; U9_6dB_c.3@4062.51,4224 4127,4224 4150.88,4247.88 4150.88,4305.54 4203.31,4357.97 4226.12,4380.78 4226.12,4386 R11_6dB_c.1@4250.12,4410
NetR11_6dB_c_2: R11_6dB_c.2 U8_6dB_c.3 | length 671.9
  Top Layer w12: v1(4515.5,4295) 4515.5,4295.5 4534.41,4314.41 U8_6dB_c.3@4606.22,4314.41
  Top Layer w15: v1(4075,4434) 4115.89,4434 R11_6dB_c.2@4139.88,4410
  MidLayer1 w15: v1(4075,4434) 4131,4434 4270,4295 v1(4515.5,4295)
NetR11_6dB_d_1: R11_6dB_d.1 R12_6dB_d.2 U9_6dB_d.3 | length 438.4
  Top Layer w15: R12_6dB_d.2@3946.12,3076.94 3970.11,3100.93 3985.93,3100.93 4013.25,3128.25 U9_6dB_d.3@4061.76,3128.25 ; U9_6dB_d.3@4062.51,3129 4127,3129 4150.88,3152.88 4150.88,3210.54 4203.31,3262.97 4226.12,3285.78 4226.12,3291 R11_6dB_d.1@4250.12,3315
NetR11_6dB_d_2: R11_6dB_d.2 U8_6dB_d.3 | length 671.9
  Top Layer w12: v1(4515.5,3200) 4515.5,3200.5 4534.41,3219.41 U8_6dB_d.3@4606.22,3219.41
  Top Layer w15: v1(4075,3339) 4115.89,3339 R11_6dB_d.2@4139.88,3315
  MidLayer1 w15: v1(4075,3339) 4131,3339 4270,3200 v1(4515.5,3200)
NetR11_12dB_a_1: R11_12dB_a.1 R12_12dB_a.2 U9_12dB_a.3 | length 439.4
  Top Layer w15: R12_12dB_a.2@2976.12,6396.94 3000.11,6420.93 3015.93,6420.93 3043.25,6448.25 3091.76,6448.25 U9_12dB_a.3@3092.51,6449 3157,6449 3180.88,6472.88 3180.88,6530.54 3233.31,6582.97 3256.12,6605.78 3256.12,6611 R11_12dB_a.1@3280.12,6635
NetR11_12dB_a_2: R11_12dB_a.2 U8_12dB_a.3 | length 672.4
  Top Layer w12: v1(3545.5,6520) 3545.5,6520.5 3564.41,6539.41 U8_12dB_a.3@3636.22,6539.41
  Top Layer w15: v1(3105,6660) 3145.89,6660 R11_12dB_a.2@3169.88,6636
  MidLayer1 w15: v1(3105,6660) 3160,6660 3300,6520 v1(3545.5,6520)
NetR11_12dB_b_1: R11_12dB_b.1 R12_12dB_b.2 U9_12dB_b.3 | length 439.4
  Top Layer w15: R12_12dB_b.2@2976.12,5306.94 3000.11,5330.93 3015.93,5330.93 3043.25,5358.25 3091.76,5358.25 U9_12dB_b.3@3092.51,5359 3157,5359 3180.88,5382.88 3180.88,5440.54 3233.31,5492.97 3256.12,5515.78 3256.12,5521 R11_12dB_b.1@3280.12,5545
NetR11_12dB_b_2: R11_12dB_b.2 U8_12dB_b.3 | length 672.4
  Top Layer w12: v1(3545.5,5430) 3545.5,5430.5 3564.41,5449.41 U8_12dB_b.3@3636.22,5449.41
  Top Layer w15: v1(3105,5570) 3145.89,5570 R11_12dB_b.2@3169.88,5546
  MidLayer1 w15: v1(3105,5570) 3160,5570 3300,5430 v1(3545.5,5430)
NetR11_12dB_c_1: R11_12dB_c.1 R12_12dB_c.2 U9_12dB_c.3 | length 438.4
  Top Layer w15: R12_12dB_c.2@2976.12,4171.94 3000.11,4195.93 3015.93,4195.93 3043.25,4223.25 U9_12dB_c.3@3091.76,4223.25 ; U9_12dB_c.3@3092.51,4224 3157,4224 3180.88,4247.88 3180.88,4305.54 3233.31,4357.97 3256.12,4380.78 3256.12,4386 R11_12dB_c.1@3280.12,4410
NetR11_12dB_c_2: R11_12dB_c.2 U8_12dB_c.3 | length 671.9
  Top Layer w12: v1(3545.5,4295) 3545.5,4295.5 3564.41,4314.41 U8_12dB_c.3@3636.22,4314.41
  Top Layer w15: v1(3105,4434) 3145.89,4434 R11_12dB_c.2@3169.88,4410
  MidLayer1 w15: v1(3105,4434) 3161,4434 3300,4295 v1(3545.5,4295)
NetR11_12dB_d_1: R11_12dB_d.1 R12_12dB_d.2 U9_12dB_d.3 | length 438.4
  Top Layer w15: R12_12dB_d.2@2976.12,3076.94 3000.11,3100.93 3015.93,3100.93 3043.25,3128.25 U9_12dB_d.3@3091.76,3128.25 ; U9_12dB_d.3@3092.51,3129 3157,3129 3180.88,3152.88 3180.88,3210.54 3233.31,3262.97 3256.12,3285.78 3256.12,3291 R11_12dB_d.1@3280.12,3315
NetR11_12dB_d_2: R11_12dB_d.2 U8_12dB_d.3 | length 671.9
  Top Layer w12: v1(3545.5,3200) 3545.5,3200.5 3564.41,3219.41 U8_12dB_d.3@3636.22,3219.41
  Top Layer w15: v1(3105,3339) 3145.89,3339 R11_12dB_d.2@3169.88,3315
  MidLayer1 w15: v1(3105,3339) 3161,3339 3300,3200 v1(3545.5,3200)
NetR11_24dB_a_1: R11_24dB_a.1 R12_24dB_a.2 U9_24dB_a.3 | length 439.4
  Top Layer w15: R12_24dB_a.2@2006.12,6396.94 2030.11,6420.93 2045.93,6420.93 2073.25,6448.25 2121.76,6448.25 U9_24dB_a.3@2122.51,6449 2187,6449 2210.88,6472.88 2210.88,6530.54 2263.31,6582.97 2286.12,6605.78 2286.12,6611 R11_24dB_a.1@2310.12,6635
NetR11_24dB_a_2: R11_24dB_a.2 U8_24dB_a.3 | length 672.4
  Top Layer w12: v1(2575.5,6520) 2575.5,6520.5 2594.41,6539.41 U8_24dB_a.3@2666.22,6539.41
  Top Layer w15: v1(2135,6660) 2175.89,6660 R11_24dB_a.2@2199.88,6636
  MidLayer1 w15: v1(2135,6660) 2190,6660 2330,6520 v1(2575.5,6520)
NetR11_24dB_b_1: R11_24dB_b.1 R12_24dB_b.2 U9_24dB_b.3 | length 439.4
  Top Layer w15: R12_24dB_b.2@2006.12,5306.94 2030.11,5330.93 2045.93,5330.93 2073.25,5358.25 2121.76,5358.25 U9_24dB_b.3@2122.51,5359 2187,5359 2210.88,5382.88 2210.88,5440.54 2263.31,5492.97 2286.12,5515.78 2286.12,5521 R11_24dB_b.1@2310.12,5545
NetR11_24dB_b_2: R11_24dB_b.2 U8_24dB_b.3 | length 672.4
  Top Layer w12: v1(2575.5,5430) 2575.5,5430.5 2594.41,5449.41 U8_24dB_b.3@2666.22,5449.41
  Top Layer w15: v1(2135,5570) 2175.89,5570 R11_24dB_b.2@2199.88,5546
  MidLayer1 w15: v1(2135,5570) 2190,5570 2330,5430 v1(2575.5,5430)
NetR11_24dB_c_1: R11_24dB_c.1 R12_24dB_c.2 U9_24dB_c.3 | length 443.4
  Top Layer w15: R12_24dB_c.2@2006.12,4168 2006.12,4171.94 2030.11,4195.93 2045.93,4195.93 2073.25,4223.25 2121.76,4223.25 U9_24dB_c.3@2122.51,4224 2187,4224 2210.88,4247.88 2210.88,4305.54 2263.31,4357.97 2286.12,4380.78 2286.12,4386 R11_24dB_c.1@2310.12,4410
NetR11_24dB_c_2: R11_24dB_c.2 U8_24dB_c.3 | length 673.4
  Top Layer w12: v1(2575.5,4295) 2575.5,4295.5 2594.41,4314.41 U8_24dB_c.3@2666.22,4314.41
  Top Layer w15: v1(2135,4435) 2175.89,4435 2199.88,4411 R11_24dB_c.2@2199.88,4410
  MidLayer1 w15: v1(2135,4435) 2190,4435 2330,4295 v1(2575.5,4295)
NetR11_24dB_d_1: R11_24dB_d.1 R12_24dB_d.2 U9_24dB_d.3 | length 438.4
  Top Layer w15: R12_24dB_d.2@2006.12,3076.94 2030.11,3100.93 2045.93,3100.93 2073.25,3128.25 U9_24dB_d.3@2121.76,3128.25 ; U9_24dB_d.3@2122.51,3129 2187,3129 2210.88,3152.88 2210.88,3210.54 2263.31,3262.97 2286.12,3285.78 2286.12,3291 R11_24dB_d.1@2310.12,3315
NetR11_24dB_d_2: R11_24dB_d.2 U8_24dB_d.3 | length 671.9
  Top Layer w12: v1(2575.5,3200) 2575.5,3200.5 2594.41,3219.41 U8_24dB_d.3@2666.22,3219.41
  Top Layer w15: v1(2135,3339) 2175.89,3339 R11_24dB_d.2@2199.88,3315
  MidLayer1 w15: v1(2135,3339) 2191,3339 2330,3200 v1(2575.5,3200)
NetR15_U_diff_in_A_2: R15_U_diff_in_A.2 R17_U_diff_in_A.1 U10_U_diff_in_A.7 | length 1768.5
  Top Layer w20: R17_U_diff_in_A.1@865.12,6300 1115,6300 1155,6340 1155,6710 1245,6800 1625,6800 1665,6760 1665,6560 1640,6535 R15_U_diff_in_A.2@1565.12,6535 ; U10_U_diff_in_A.7@1013.5,6391.5 U10_U_diff_in_A.7@974.53,6391.5 1153.5,6391.5
NetR15_U_diff_in_B_2: R15_U_diff_in_B.2 R17_U_diff_in_B.1 U10_U_diff_in_B.7 | length 1768.5
  Top Layer w20: R17_U_diff_in_B.1@865.12,5320 1115,5320 1155,5360 1155,5730 1245,5820 1625,5820 1665,5780 1665,5580 1640,5555 R15_U_diff_in_B.2@1565.12,5555 ; U10_U_diff_in_B.7@1013.5,5411.5 U10_U_diff_in_B.7@974.53,5411.5 1153.5,5411.5
NetR15_U_diff_in_C_2: R15_U_diff_in_C.2 R17_U_diff_in_C.1 U10_U_diff_in_C.7 | length 1768.5
  Top Layer w20: R17_U_diff_in_C.1@865.12,4195 1115,4195 1155,4235 1155,4605 1245,4695 1625,4695 1665,4655 1665,4455 1640,4430 R15_U_diff_in_C.2@1565.12,4430 ; U10_U_diff_in_C.7@1013.5,4286.5 U10_U_diff_in_C.7@974.53,4286.5 1153.5,4286.5
NetR15_U_diff_in_D_2: R15_U_diff_in_D.2 R17_U_diff_in_D.1 U10_U_diff_in_D.7 | length 1768.5
  Top Layer w20: R17_U_diff_in_D.1@865.12,3075 1115,3075 1155,3115 1155,3485 1245,3575 1625,3575 1665,3535 1665,3335 1640,3310 R15_U_diff_in_D.2@1565.12,3310 ; U10_U_diff_in_D.7@1013.5,3166.5 U10_U_diff_in_D.7@974.53,3166.5 1153.5,3166.5
NetR17_U_diff_in_A_2: R17_U_diff_in_A.2 R18_U_diff_in_A.2 U10_U_diff_in_A.6 | length 830.8
  Top Layer w15: v1@660,6450 660,6330 690,6300 R17_U_diff_in_A.2@754.88,6300 ; v1(670,6460) 694.88,6484.88 R18_U_diff_in_A.2@760,6484.88 ; U10_U_diff_in_A.6@974.53,6441.5 978.03,6445 v1(1070,6445)
  MidLayer1 w15: v1(670,6460) 685,6445 v1(1070,6445)
NetR17_U_diff_in_B_2: R17_U_diff_in_B.2 R18_U_diff_in_B.2 U10_U_diff_in_B.6 | length 854.9
  Top Layer w15: R17_U_diff_in_B.2@754.88,5320 690,5320 660,5350 660,5470 v1(670,5480) 694.88,5504.88 R18_U_diff_in_B.2@760,5504.88 ; U10_U_diff_in_B.6@974.53,5461.5 978.03,5465 v1(1075,5465)
  MidLayer1 w15: v1(670,5480) 685,5465 v1(1075,5465)
NetR17_U_diff_in_C_2: R17_U_diff_in_C.2 R18_U_diff_in_C.2 U10_U_diff_in_C.6 | length 828.5
  Top Layer w15: R17_U_diff_in_C.2@754.88,4195 690,4195 660,4225 660,4345 v1(670,4355) 694.88,4379.88 R18_U_diff_in_C.2@760,4379.88 ; U10_U_diff_in_C.6@974.53,4336.5 v1(1070,4340)
  MidLayer1 w15: v1(670,4355) 685,4340 v1@1055,4340
NetR17_U_diff_in_D_2: R17_U_diff_in_D.2 R18_U_diff_in_D.2 U10_U_diff_in_D.6 | length 854.9
  Top Layer w15: R17_U_diff_in_D.2@754.88,3075 690,3075 660,3105 660,3225 v1(670,3235) 694.88,3259.88 R18_U_diff_in_D.2@760,3259.88 ; U10_U_diff_in_D.6@974.53,3216.5 978.03,3220 v1(1075,3220)
  MidLayer1 w15: v1(670,3235) 685,3220 v1(1075,3220)
NetR18_U_diff_in_A_1: R18_U_diff_in_A.1 R19_U_diff_in_A.2 U10_U_diff_in_A.2 | length 887.4
  Top Layer w20: R19_U_diff_in_A.2@754.88,6780 685,6780 655,6750 v1(655,6625) 684.88,6595.12 R18_U_diff_in_A.1@760,6595.12 ; U10_U_diff_in_A.2@974.53,6641.5 1068.5,6641.5 v1(1075,6635)
  MidLayer1 w20: v1(655,6625) 671.5,6641.5 1068.5,6641.5 v1(1075,6635)
NetR18_U_diff_in_B_1: R18_U_diff_in_B.1 R19_U_diff_in_B.2 U10_U_diff_in_B.2 | length 917.4
  Top Layer w20: R19_U_diff_in_B.2@754.88,5800 685,5800 655,5770 v1(655,5645) 684.88,5615.12 R18_U_diff_in_B.1@760,5615.12 ; U10_U_diff_in_B.2@974.53,5661.5 1051.5,5661.5 1057.99,5655 v1(1090,5655)
  MidLayer1 w20: v1(655,5645) 671.5,5661.5 1051.5,5661.5 1057.99,5655 v1(1090,5655)
NetR18_U_diff_in_C_1: R18_U_diff_in_C.1 R19_U_diff_in_C.2 U10_U_diff_in_C.2 | length 917.4
  Top Layer w20: R19_U_diff_in_C.2@754.88,4675 685,4675 655,4645 v1(655,4520) 684.88,4490.12 R18_U_diff_in_C.1@760,4490.12 ; U10_U_diff_in_C.2@974.53,4536.5 1051.5,4536.5 1057.99,4530 v1(1090,4530)
  MidLayer1 w20: v1(655,4520) 671.5,4536.5 1051.5,4536.5 1057.99,4530 v1(1090,4530)
NetR18_U_diff_in_D_1: R18_U_diff_in_D.1 R19_U_diff_in_D.2 U10_U_diff_in_D.2 | length 893.2
  Top Layer w20: R19_U_diff_in_D.2@754.88,3555 685,3555 655,3525 v1(655,3400) 684.88,3370.12 R18_U_diff_in_D.1@760,3370.12 ; U10_U_diff_in_D.2@974.53,3416.5 1051.5,3416.5 1052.99,3415 v1(1080,3415)
  MidLayer1 w20: v1(655,3400) 671.5,3416.5 1051.5,3416.5 1052.99,3415 v1(1080,3415)
NetR19_U_diff_in_A_1: R19_U_diff_in_A.1 R21_U_diff_in_A.2 U10_U_diff_in_A.1 | length 1405.3
  Top Layer w20: R19_U_diff_in_A.1@865.12,6780 980,6780 1035,6835 1640,6835 1700,6775 1700,6500 1640,6440 R21_U_diff_in_A.2@1565.12,6440 ; U10_U_diff_in_A.1@974.53,6691.5 974.53,6779.53
NetR19_U_diff_in_B_1: R19_U_diff_in_B.1 R21_U_diff_in_B.2 U10_U_diff_in_B.1 | length 1405.3
  Top Layer w20: R19_U_diff_in_B.1@865.12,5800 980,5800 1035,5855 1640,5855 1700,5795 1700,5520 1640,5460 R21_U_diff_in_B.2@1565.12,5460 ; U10_U_diff_in_B.1@974.53,5711.5 974.53,5799.53
NetR19_U_diff_in_C_1: R19_U_diff_in_C.1 R21_U_diff_in_C.2 U10_U_diff_in_C.1 | length 1405.3
  Top Layer w20: R19_U_diff_in_C.1@865.12,4675 980,4675 1035,4730 1640,4730 1700,4670 1700,4395 1640,4335 R21_U_diff_in_C.2@1565.12,4335 ; U10_U_diff_in_C.1@974.53,4586.5 974.53,4674.53
NetR19_U_diff_in_D_1: R19_U_diff_in_D.1 R21_U_diff_in_D.2 U10_U_diff_in_D.1 | length 1405.3
  Top Layer w20: R19_U_diff_in_D.1@865.12,3555 980,3555 1035,3610 1640,3610 1700,3550 1700,3275 1640,3215 R21_U_diff_in_D.2@1565.12,3215 ; U10_U_diff_in_D.1@974.53,3466.5 974.53,3554.53
NetR23_U_diff_out_A_1: R23_U_diff_out_A.1 R25_U_diff_out_A.2 TP7_U_diff_out_A.1 U11_U_diff_out_A.1 | length 305.2
  Top Layer w15: R23_U_diff_out_A.1@6269.37,2029.49 R23_U_diff_out_A.1@6274.88,2035
  Top Layer w20: U11_U_diff_out_A.1@6195,2029.49 R23_U_diff_out_A.1@6269.37,2029.49 ; R23_U_diff_out_A.1@6274.88,2035 6274.88,2070.12 6255.12,2089.88 R25_U_diff_out_A.2@6255.12,2130 TP7_U_diff_out_A.1@6375,2130
NetR23_U_diff_out_B_1: R23_U_diff_out_B.1 R25_U_diff_out_B.2 TP7_U_diff_out_B.1 U11_U_diff_out_B.1 | length 305.2
  Top Layer w15: R23_U_diff_out_B.1@7504.37,2029.49 R23_U_diff_out_B.1@7509.88,2035
  Top Layer w20: U11_U_diff_out_B.1@7430,2029.49 R23_U_diff_out_B.1@7504.37,2029.49 ; R23_U_diff_out_B.1@7509.88,2035 7509.88,2070.12 7490.12,2089.88 R25_U_diff_out_B.2@7490.12,2130 TP7_U_diff_out_B.1@7610,2130
NetR23_U_diff_out_C_1: R23_U_diff_out_C.1 R25_U_diff_out_C.2 TP7_U_diff_out_C.1 U11_U_diff_out_C.1 | length 305.2
  Top Layer w15: R23_U_diff_out_C.1@6264.37,1314.49 R23_U_diff_out_C.1@6269.88,1320
  Top Layer w20: U11_U_diff_out_C.1@6190,1314.49 R23_U_diff_out_C.1@6264.37,1314.49 ; R23_U_diff_out_C.1@6269.88,1320 6269.88,1355.12 6250.12,1374.88 R25_U_diff_out_C.2@6250.12,1415 TP7_U_diff_out_C.1@6370,1415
